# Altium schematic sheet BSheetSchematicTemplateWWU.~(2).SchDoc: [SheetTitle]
size B; Date: [Date]
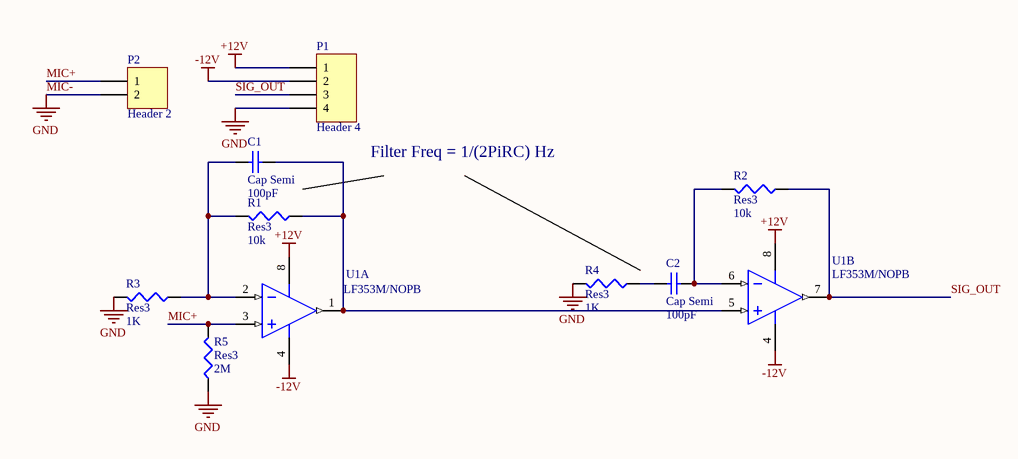
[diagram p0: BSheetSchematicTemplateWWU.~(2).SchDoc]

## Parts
C1  Cap Semi  value 100pF  [1608[0603]]
C2  Cap Semi  value 100pF  [1608[0603]]
P1  Header 4  [HDR1X4]
P2  Header 2  [HDR1X2]
R1  Res3  value 10k  [J1-0603]
R2  Res3  value 10k  [J1-0603]
R3  Res3  value 1K  [J1-0603]
R4  Res3  value 1K  [J1-0603]
R5  Res3  value 2M  [J1-0603]
U1  LF353M/NOPB  [D0008A_M]  (parts A,B of 2)

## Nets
+12V: P1.1 U1.8(V+)
-12V: P1.2 U1.4(V-)
MIC-: P1.4 P2.2 R3.2 R4.2 R5.1  [also labelled GND]
MIC+: P2.1 R5.2 U1.3(INA+)
SIG_OUT: P1.3 R2.1 U1.7(OUTB)
NetC1_1: C1.1 R1.2 R3.1 U1.2(INA-)
NetC1_2: C1.2 R1.1 U1.1(OUTA) U1.5(INB+)
NetC2_1: C2.1 R4.1
NetC2_2: C2.2 R2.2 U1.6(INB-)

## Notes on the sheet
- Filter Freq = 1/(2PiRC) Hz

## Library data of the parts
C1 C2 = Cap Semi: Capacitor (Semiconductor SIM Model)
P1 = Header 4: Header, 4-Pin
P2 = Header 2: Header, 2-Pin
R1-R5 = Res3: Resistor
U1 = CMP-0055-00856-3: Wide Bandwidth Dual JFET Input Operational Amplifier, 8-pin Narrow SOIC, Pb-Free; Manufacturer: Texas Instruments; PackageTopMarking: NSZXTT*LF353*M; CompType: Amplifiers; PowerWise: N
